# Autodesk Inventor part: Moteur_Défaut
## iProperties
Shininess: 64.0
Length Units: 11269
Angle Units: 11279
Time Units: 11290
Mass Units: 11283
Length Display Precision: 3
Angle Display Precision: 2
Compacted: True
Part Number: Moteur_Défaut
Document SubType Name: Modeling
Created: 2006-01
Material: Par défaut
Designer: Fricot
Density: 0.0
Volumn: 0.0
Area: 0.0
PropertySet Name: Model Information
Control State: 0
Master: False
Checked Out: False
Author: Fricot
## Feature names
1. Base1
